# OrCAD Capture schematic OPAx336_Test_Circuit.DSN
size A; title: OPAx336, SINGLE-SUPPLY, microPower CMOS OPERATIONAL; rev: 1.3; note: Datasheet: SBOS068C EVM: N/A
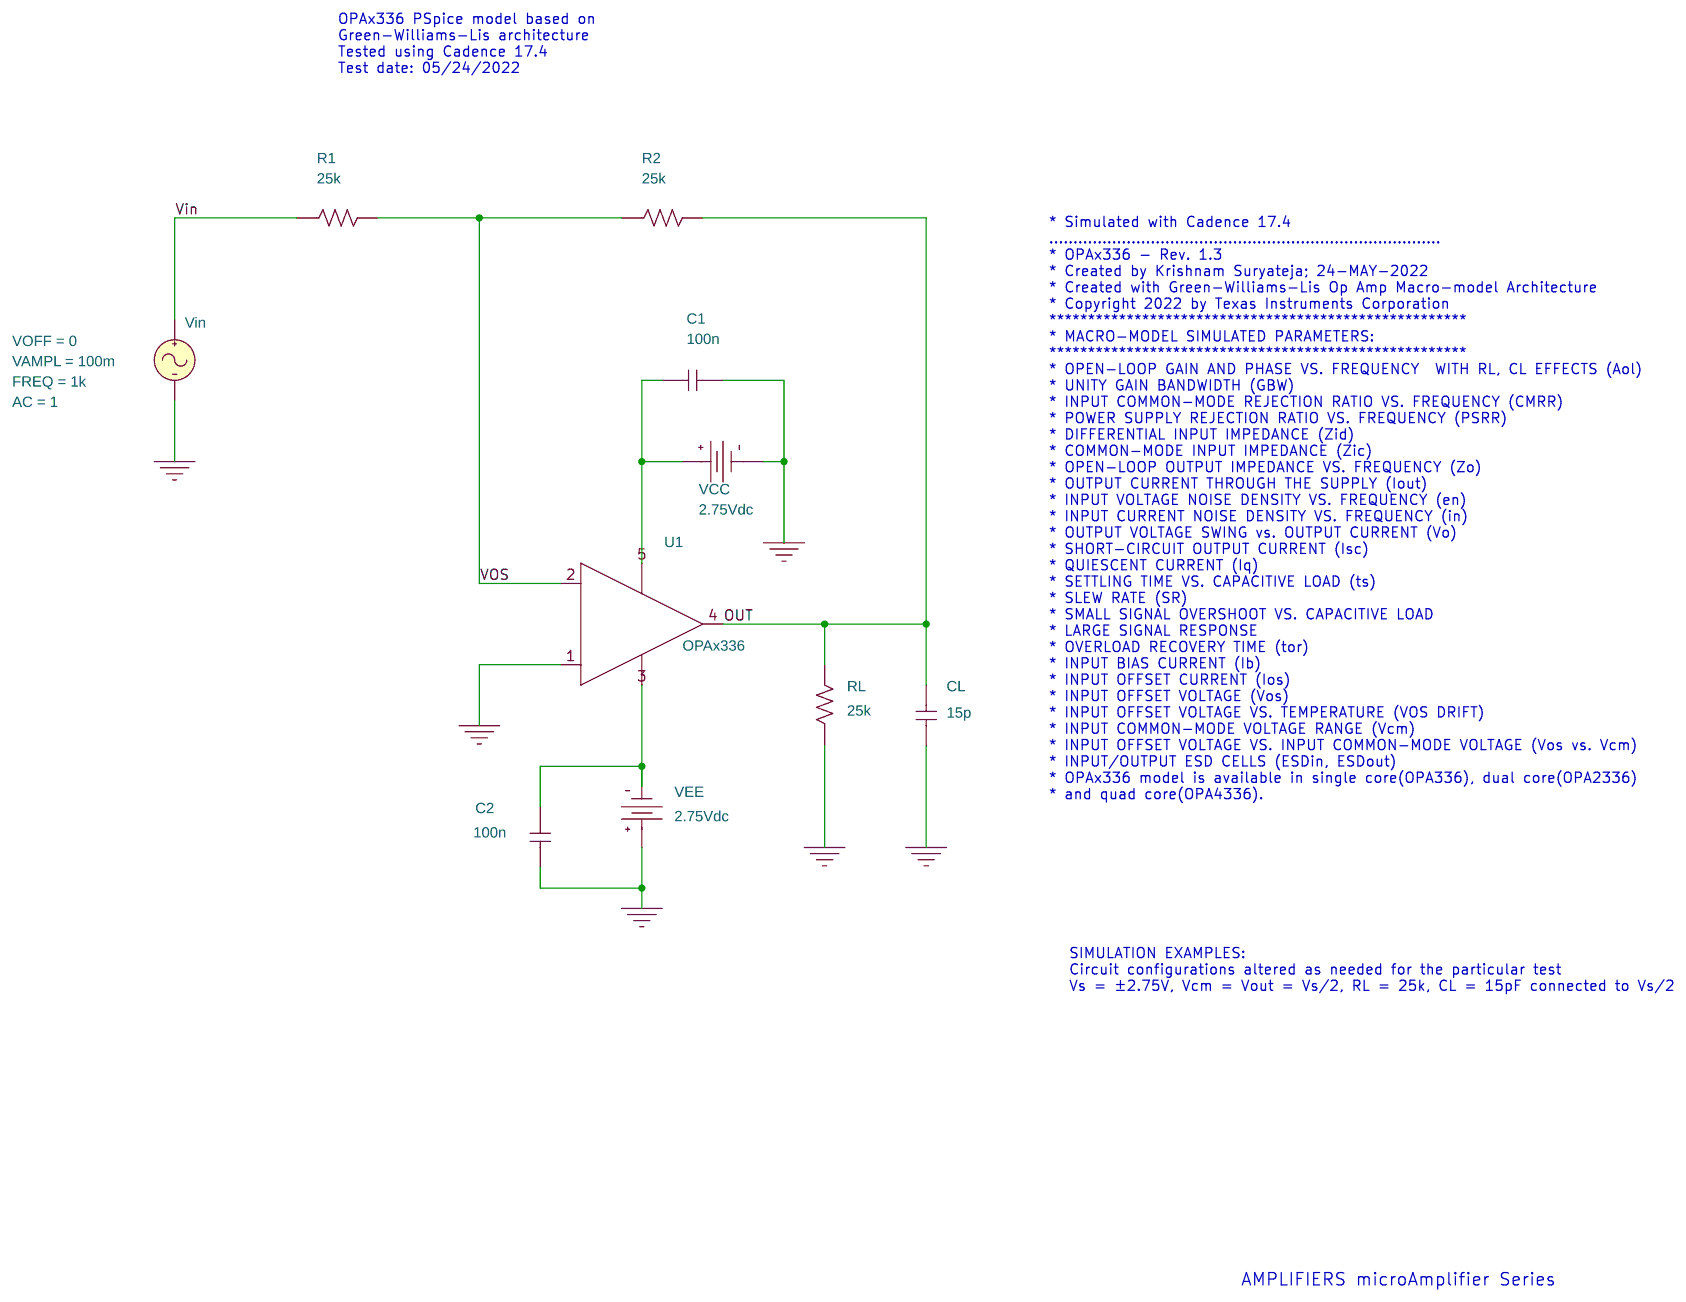
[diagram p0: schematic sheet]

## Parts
C1  100n  [cap196]
C2  100n  [cap196]
CL  15p  [cap196]
R1  25k  [AXRC05]
R2  25k  [AXRC05]
RL  25k  [AXRC05]
U1  OPAx336
VCC  VDC
VEE  VDC
Vin  VSIN

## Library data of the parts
C1 C2 CL = C
R1 R2 RL = R
U1 = OPAx336
VCC VEE = VDC: DC: 2.75Vdc
Vin = VSIN: AC: 1; FREQ: 1k; VAMPL: 100m; VOFF: 0

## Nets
Vin: R1.1 Vin.1(+)
0: C1.2 C2.1 CL.2 RL.1 U1.1(+) VCC.1(-) VEE.0(+) Vin.2(-)
OUT: CL.1 R2.2 RL.2 U1.4(OUT)
VOS: R1.2 R2.1 U1.2(-)
N27303: C1.1 U1.5(V+) VCC.0(+)
N27354: C2.2 U1.3(V-) VEE.1(-)

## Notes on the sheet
- OPAx336 PSpice model based on
  Green-Williams-Lis architecture
  Tested using Cadence 17.4
  Test date: 05/24/2022
- * Simulated with Cadence 17.4
  .................................................................................
  * OPAx336 - Rev. 1.3
  * Created by Krishnam Suryateja; 24-MAY-2022
  * Created with Green-Williams-Lis Op Amp Macro-model Architecture
  * Copyright 2022 by Texas Instruments Corporation
  ******************************************************
  * MACRO-MODEL SIMULATED PARAMETERS:
  ******************************************************
  * OPEN-LOOP GAIN AND PHASE VS. FREQUENCY  WITH RL, CL EFFECTS (Aol)
  * UNITY GAIN BANDWIDTH (GBW)
  * INPUT COMMON-MODE REJECTION RATIO VS. FREQUENCY (CMRR)
  * POWER SUPPLY REJECTION RATIO VS. FREQUENCY (PSRR)
  * DIFFERENTIAL INPUT IMPEDANCE (Zid)
  * COMMON-MODE INPUT IMPEDANCE (Zic)
  * OPEN-LOOP OUTPUT IMPEDANCE VS. FREQUENCY (Zo)
  * OUTPUT CURRENT THROUGH THE SUPPLY (Iout)
  * INPUT VOLTAGE NOISE DENSITY VS. FREQUENCY (en)
  * INPUT CURRENT NOISE DENSITY VS. FREQUENCY (in)
  * OUTPUT VOLTAGE SWING vs. OUTPUT CURRENT (Vo)
  * SHORT-CIRCUIT OUTPUT CURRENT (Isc)
  * QUIESCENT CURRENT (Iq)
  * SETTLING TIME VS. CAPACITIVE LOAD (ts)
  * SLEW RATE (SR)
  * SMALL SIGNAL OVERSHOOT VS. CAPACITIVE LOAD
  * LARGE SIGNAL RESPONSE
  * OVERLOAD RECOVERY TIME (tor)
  * INPUT BIAS CURRENT (Ib)
  * INPUT OFFSET CURRENT (Ios)
  * INPUT OFFSET VOLTAGE (Vos)
  * INPUT OFFSET VOLTAGE VS. TEMPERATURE (VOS DRIFT)
  * INPUT COMMON-MODE VOLTAGE RANGE (Vcm)
  * INPUT OFFSET VOLTAGE VS. INPUT COMMON-MODE VOLTAGE (Vos vs. Vcm)
  * INPUT/OUTPUT ESD CELLS (ESDin, ESDout)
  * OPAx336 model is available in single core(OPA336), dual core(OPA2336)
  * and quad core(OPA4336).
- SIMULATION EXAMPLES:
  Circuit configurations altered as needed for the particular test
  Vs = ±2.75V, Vcm = Vout = Vs/2, RL = 25k, CL = 15pF connected to Vs/2
- AMPLIFIERS microAmplifier Series
